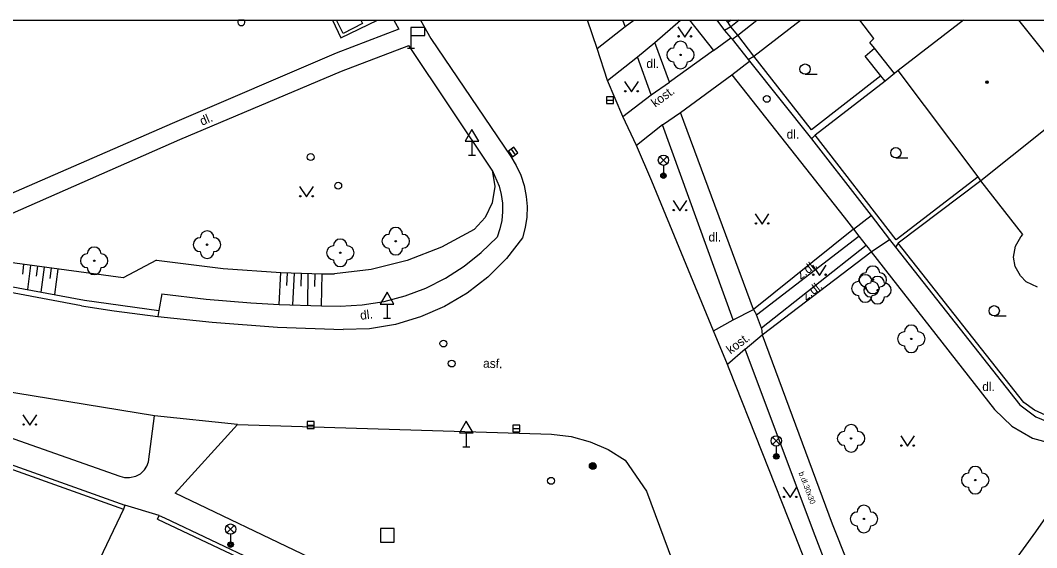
# Model space of a CAD drawing. Extents: x -600309 to -598967, y -1161267 to -1160292.
# Drawn here: x -600107.7 to -600033.9, y -1160330.6 to -1160292.3 of the extents above; entities that cross this region are included whole.
import ezdxf

# ---------------------------------------------------------------- set-up
doc = ezdxf.new("R2010")
doc.units = 0
for name, color, linetype in [('Level 10', 7, 'Continuous'), ('Level 11', 7, 'Continuous'), ('Level 14', 7, 'Continuous'), ('Level 15', 7, 'Continuous'), ('Level 22', 7, 'Continuous'), ('Level 25', 7, 'Continuous'), ('Level 26', 7, 'Continuous'), ('Level 27', 7, 'Continuous'), ('Level 28', 7, 'Continuous'), ('Level 33', 7, 'Continuous'), ('Level 34', 7, 'Continuous'), ('Level 36', 7, 'Continuous'), ('Level 39', 7, 'Continuous'), ('Level 40', 7, 'Continuous'), ('Level 5', 7, 'Continuous'), ('Level 7', 7, 'Continuous'), ('Level 8', 7, 'Continuous'), ('Vrstva 28', 7, 'Continuous'), ('Vrstva 63', 7, 'Continuous')]:
    doc.layers.add(name, color=color, linetype=linetype)

msp = doc.modelspace()

# ---------------------------------------------------------------- linework, layer by layer
at = {"layer": 'Level 10'}
for p, q in [((-600078.6368, -1160292.3474), (-600077.89, -1160293.6599)), ((-600065.81, -1160294.39), (-600066.5144, -1160292.3474))]:
    msp.add_line(p, q, dxfattribs=at)
for points in [[(-600077.89, -1160293.6599), (-600072.07, -1160302.23)], [(-600065.06, -1160296.71), (-600065.81, -1160294.39)], [(-600063.95, -1160299.33), (-600065.06, -1160296.71)], [(-600062.95, -1160301.43), (-600063.95, -1160299.33)], [(-600056.22, -1160317.66), (-600056.35, -1160317.35), (-600057.36, -1160314.89), (-600061.84, -1160304.04), (-600062.95, -1160301.43)], [(-600072.07, -1160302.23), (-600071.68, -1160302.89), (-600071.36, -1160303.6), (-600071.12, -1160304.34), (-600070.9699, -1160305.15), (-600070.9, -1160305.86), (-600070.92, -1160306.64), (-600071.03, -1160307.4), (-600071.2199, -1160308.15)], [(-600071.2199, -1160308.15), (-600072.39, -1160309.65), (-600073.74, -1160310.99), (-600075.25, -1160312.1599), (-600076.89, -1160313.13), (-600078.63, -1160313.89), (-600080.46, -1160314.43), (-600082.34, -1160314.74), (-600084.24, -1160314.81)], [(-600103.23, -1160313.09), (-600115.49, -1160310.79)], [(-600103.23, -1160313.09), (-600100.87, -1160313.44), (-600097.7, -1160313.85)], [(-600097.7, -1160313.85), (-600093.76, -1160314.26), (-600089.01, -1160314.62), (-600084.24, -1160314.81)], [(-600051.43, -1160329.77), (-600056.22, -1160317.66)], [(-600097.95, -1160321.06), (-600115.58, -1160318.2)], [(-600091.93, -1160321.69), (-600097.95, -1160321.06)], [(-600091.93, -1160321.69), (-600069.13, -1160322.4099)], [(-600069.13, -1160322.4099), (-600067.71, -1160322.58), (-600066.32, -1160322.95), (-600065.01, -1160323.52), (-600063.79, -1160324.28)], [(-600063.79, -1160324.28), (-600062.23, -1160326.55)], [(-600062.23, -1160326.55), (-600056.25, -1160342.63)], [(-600047.36, -1160339.81), (-600048.12, -1160338.24), (-600051.43, -1160329.77)]]:
    msp.add_lwpolyline(points, dxfattribs=at)
at = {"layer": 'Level 11'}
for p, q in [((-600085.0266, -1160292.3474), (-600084.42, -1160293.61)), ((-600084.42, -1160293.61), (-600081.7545, -1160292.3474)), ((-600080.5637, -1160292.3474), (-600080.21, -1160292.99)), ((-600063.78, -1160292.8), (-600063.9425, -1160292.3474)), ((-600063.78, -1160292.8), (-600063.1463, -1160292.3474)), ((-600061.62, -1160293.9699), (-600059.7561, -1160292.3474)), ((-600059.1186, -1160292.3474), (-600057.36, -1160294.55)), ((-600055.61, -1160293.42), (-600054.2316, -1160292.3474)), ((-600054.43, -1160294.94), (-600051.0474, -1160292.3474))]:
    msp.add_line(p, q, dxfattribs=at)
for points in [[(-600082.9585, -1160292.3474), (-600082.84, -1160292.58), (-600084.24, -1160293.31), (-600084.7292, -1160292.3474)], [(-600065.81, -1160294.39), (-600063.78, -1160292.8)], [(-600056.12, -1160292.82), (-600056.31, -1160292.51)], [(-600080.21, -1160292.99), (-600084.75, -1160294.74)], [(-600057.36, -1160294.55), (-600056.1, -1160293.62)], [(-600054.43, -1160294.94), (-600055.61, -1160293.42)], [(-600084.37, -1160296.03), (-600079.48, -1160294.18)], [(-600073.44, -1160303.24), (-600079.48, -1160294.18)], [(-600062.89, -1160295.01), (-600061.62, -1160293.9699)], [(-600060.55, -1160296.84), (-600061.62, -1160293.9699)], [(-600046.37, -1160294.94), (-600045.69, -1160294.38)], [(-600084.75, -1160294.74), (-600096.65, -1160299.84)], [(-600065.06, -1160296.71), (-600062.89, -1160295.01)], [(-600061.89, -1160297.77), (-600062.89, -1160295.01)], [(-600057.36, -1160294.55), (-600060.55, -1160296.84)], [(-600045.2199, -1160296.37), (-600046.37, -1160294.94)], [(-600056.03, -1160296.3), (-600054.75, -1160295.32)], [(-600096.11, -1160301.01), (-600084.37, -1160296.03)], [(-600059.76, -1160299.05), (-600056.03, -1160296.3)], [(-600056.03, -1160296.3), (-600047.89, -1160306.65), (-600047.21, -1160307.51)], [(-600061.89, -1160297.77), (-600060.55, -1160296.84)], [(-600063.95, -1160299.33), (-600061.89, -1160297.77)], [(-600061.08, -1160299.93), (-600059.76, -1160299.05)], [(-600054.46, -1160313.36), (-600059.76, -1160299.05)], [(-600096.65, -1160299.84), (-600114.78, -1160307.74)], [(-600061.08, -1160299.93), (-600062.95, -1160301.43)], [(-600055.93, -1160314.1), (-600061.08, -1160299.93)], [(-600108.25, -1160306.36), (-600096.11, -1160301.01)], [(-600073.44, -1160303.24), (-600072.93, -1160304.39), (-600072.78, -1160305), (-600072.69, -1160305.63), (-600072.68, -1160306.26), (-600072.74, -1160306.89), (-600072.87, -1160307.5), (-600073.07, -1160308.1)], [(-600047.21, -1160307.51), (-600045.93, -1160306.53)], [(-600047.21, -1160307.51), (-600054.46, -1160313.36)], [(-600047.21, -1160307.51), (-600046.81, -1160308.02)], [(-600084.46, -1160313.11), (-600082.86, -1160313.02), (-600081.28, -1160312.77), (-600079.74, -1160312.36), (-600078.24, -1160311.79), (-600076.82, -1160311.07), (-600075.4699, -1160310.21), (-600074.2199, -1160309.2199), (-600073.07, -1160308.1)], [(-600054.25, -1160313.74), (-600046.81, -1160308.02)], [(-600046.81, -1160308.02), (-600046.28, -1160308.71)], [(-600045.93, -1160309.1599), (-600044.59, -1160308.26)], [(-600046.28, -1160308.71), (-600053.88, -1160314.71)], [(-600053.83, -1160315.19), (-600045.93, -1160309.1599)], [(-600046.28, -1160308.71), (-600046.15, -1160308.87), (-600045.93, -1160309.1599)], [(-600045.93, -1160309.1599), (-600036.98, -1160320.62)], [(-600097.4099, -1160312.2199), (-600097.63, -1160313.4099)], [(-600097.4099, -1160312.2199), (-600094.19, -1160312.59), (-600090.95, -1160312.87), (-600088.89, -1160312.99), (-600085.82, -1160313.09), (-600084.46, -1160313.11)], [(-600097.63, -1160313.4099), (-600097.7, -1160313.85)], [(-600055.93, -1160314.1), (-600054.46, -1160313.36)], [(-600054.46, -1160313.36), (-600054.25, -1160313.74)], [(-600057.36, -1160314.89), (-600055.93, -1160314.1)], [(-600053.88, -1160314.71), (-600054.25, -1160313.74)], [(-600053.88, -1160314.71), (-600053.83, -1160315.19)], [(-600055.08, -1160316.23), (-600053.83, -1160315.19)], [(-600053.83, -1160315.19), (-600048.76, -1160328.92), (-600047.67, -1160331.66)], [(-600055.08, -1160316.23), (-600056.35, -1160317.35)], [(-600048.59, -1160333.43), (-600050.11, -1160329.48), (-600055.08, -1160316.23)], [(-600114.56, -1160320.48), (-600100.45, -1160325.46)], [(-600036.98, -1160320.62), (-600035.7199, -1160321.83), (-600034.21, -1160322.69), (-600032.53, -1160323.1599), (-600030.79, -1160323.2)], [(-600098.39, -1160324.4), (-600097.95, -1160321.06)], [(-600062.78, -1160347.75), (-600066.6599, -1160344.9099), (-600073.81, -1160339.63), (-600081.26, -1160334.63), (-600086.65, -1160331.38), (-600096.45, -1160326.68), (-600091.93, -1160321.69)], [(-600100.45, -1160325.46), (-600100.12, -1160325.55), (-600099.75, -1160325.56), (-600099.3, -1160325.46), (-600098.9699, -1160325.27), (-600098.67, -1160324.98), (-600098.51, -1160324.73), (-600098.39, -1160324.4)], [(-600030.89, -1160325.06), (-600034, -1160329.49)], [(-600034, -1160329.49), (-600040.85, -1160338.94)]]:
    msp.add_lwpolyline(points, dxfattribs=at)
at = {"layer": 'Level 14'}
for points in [[(-600073.44, -1160303.24), (-600073.25, -1160304.4099), (-600073.43, -1160305.59), (-600073.94, -1160306.6599), (-600074.75, -1160307.53)], [(-600074.75, -1160307.53), (-600077.11, -1160308.82), (-600079.61, -1160309.8), (-600082.21, -1160310.45), (-600084.88, -1160310.76)], [(-600097.8, -1160309.76), (-600100.2199, -1160311.06), (-600114.53, -1160309.11)], [(-600097.8, -1160309.76), (-600092.9699, -1160310.37), (-600088.78, -1160310.6599), (-600085.78, -1160310.75), (-600084.88, -1160310.76)], [(-600115.4099, -1160310.36), (-600103.03, -1160312.67), (-600097.63, -1160313.4099)]]:
    msp.add_lwpolyline(points, dxfattribs=at)
at = {"layer": 'Level 15'}
for points in [[(-600107.44, -1160310.08), (-600107.53, -1160310.78)], [(-600106.94, -1160310.15), (-600107.17, -1160311.9)], [(-600106.44, -1160310.21), (-600106.54, -1160310.93)], [(-600105.95, -1160310.28), (-600106.19, -1160312.08)], [(-600105.45, -1160310.35), (-600105.55, -1160311.09)], [(-600104.96, -1160310.4099), (-600105.2, -1160312.26)], [(-600088.89, -1160312.99), (-600088.78, -1160310.6599)], [(-600088.33, -1160311.61), (-600088.28, -1160310.68)], [(-600087.89, -1160313.02), (-600087.78, -1160310.7)], [(-600087.3, -1160311.65), (-600087.28, -1160310.71)], [(-600086.82, -1160313.06), (-600086.78, -1160310.7199)], [(-600086.3, -1160311.68), (-600086.28, -1160310.74)], [(-600085.82, -1160313.09), (-600085.78, -1160310.75)]]:
    msp.add_lwpolyline(points, dxfattribs=at)
at = {"layer": 'Level 22'}
for centre in [(-600059.76, -1160294.86), (-600080.43, -1160308.39), (-600094.13, -1160308.64), (-600102.32, -1160309.81), (-600084.46, -1160309.23), (-600045.8, -1160311.19), (-600046.35, -1160311.82), (-600045.46, -1160311.94), (-600043.01, -1160315.48), (-600047.38, -1160322.71), (-600038.37, -1160325.74), (-600046.45, -1160328.56)]:
    msp.add_circle(centre, 0.05, dxfattribs=at)
for centre, start, end in [((-600060.26, -1160294.86), 90, 270), ((-600059.76, -1160294.36), 0, 180), ((-600059.26, -1160294.86), 270, 90), ((-600059.76, -1160295.36), 180, 0), ((-600094.13, -1160308.14), 0, 180), ((-600080.43, -1160307.89), 0, 180), ((-600094.63, -1160308.64), 90, 270), ((-600093.63, -1160308.64), 270, 90), ((-600084.46, -1160308.73), 0, 180), ((-600080.93, -1160308.39), 90, 270), ((-600079.93, -1160308.39), 270, 90), ((-600102.32, -1160309.31), 0, 180), ((-600094.13, -1160309.14), 180, 0), ((-600084.96, -1160309.23), 90, 270), ((-600083.96, -1160309.23), 270, 90), ((-600080.43, -1160308.89), 180, 0), ((-600102.82, -1160309.81), 90, 270), ((-600101.82, -1160309.81), 270, 90), ((-600084.46, -1160309.73), 180, 0), ((-600102.32, -1160310.31), 180, 0), ((-600045.8, -1160310.69), 0, 180), ((-600046.85, -1160311.82), 90, 270), ((-600046.35, -1160311.32), 0, 180), ((-600046.3, -1160311.19), 90, 270), ((-600045.46, -1160311.44), 0, 180), ((-600045.85, -1160311.82), 270, 90), ((-600045.3, -1160311.19), 270, 90), ((-600045.96, -1160311.94), 90, 270), ((-600045.8, -1160311.69), 180, 0), ((-600044.96, -1160311.94), 270, 90), ((-600046.35, -1160312.32), 180, 0), ((-600045.46, -1160312.44), 180, 0), ((-600043.51, -1160315.48), 90, 270), ((-600043.01, -1160314.98), 0, 180), ((-600042.51, -1160315.48), 270, 90), ((-600043.01, -1160315.98), 180, 0), ((-600047.88, -1160322.71), 90, 270), ((-600047.38, -1160322.21), 0, 180), ((-600046.88, -1160322.71), 270, 90), ((-600047.38, -1160323.21), 180, 0), ((-600038.87, -1160325.74), 90, 270), ((-600038.37, -1160325.24), 0, 180), ((-600037.87, -1160325.74), 270, 90), ((-600038.37, -1160326.24), 180, 0), ((-600046.45, -1160328.06), 0, 180), ((-600046.95, -1160328.56), 90, 270), ((-600045.95, -1160328.56), 270, 90), ((-600046.45, -1160329.06), 180, 0)]:
    msp.add_arc(centre, 0.5, start, end, dxfattribs=at)
at = {"layer": 'Level 25'}
for radius in [0.25, 0.2, 0.15, 0.1, 0.05]:
    msp.add_circle((-600066.13, -1160324.7199), radius, dxfattribs=at)
at = {"layer": 'Level 26'}
msp.add_lwpolyline([(-600081.54, -1160330.25), (-600080.54, -1160330.25), (-600080.54, -1160329.25), (-600081.54, -1160329.25)], close=True, dxfattribs=at)
at = {"layer": 'Level 27'}
for p, q in [((-600065.13, -1160298.15), (-600064.63, -1160298.15)), ((-600072.0551, -1160301.7165), (-600071.7647, -1160302.1235)), ((-600086.85, -1160321.74), (-600086.35, -1160321.74)), ((-600071.93, -1160321.99), (-600071.43, -1160321.99))]:
    msp.add_line(p, q, dxfattribs=at)
for points in [[(-600065.13, -1160298.4), (-600064.63, -1160298.4), (-600064.63, -1160297.9), (-600065.13, -1160297.9)], [(-600072.2586, -1160301.8617), (-600071.9682, -1160302.2687), (-600071.5612, -1160301.9783), (-600071.8516, -1160301.5713)], [(-600086.85, -1160321.99), (-600086.35, -1160321.99), (-600086.35, -1160321.49), (-600086.85, -1160321.49)], [(-600071.93, -1160322.24), (-600071.43, -1160322.24), (-600071.43, -1160321.74), (-600071.93, -1160321.74)]]:
    msp.add_lwpolyline(points, close=True, dxfattribs=at)
at = {"layer": 'Level 28'}
for centre in [(-600053.5, -1160298.05), (-600086.6, -1160302.28), (-600084.61, -1160304.36), (-600076.9699, -1160315.82), (-600076.37, -1160317.27), (-600069.1599, -1160325.79)]:
    msp.add_circle(centre, 0.25, dxfattribs=at)
at = {"layer": 'Level 33'}
for p, q in [((-600061.265, -1160302.77), (-600060.735, -1160302.24)), ((-600061.265, -1160302.24), (-600060.735, -1160302.77)), ((-600061, -1160302.88), (-600061, -1160303.63)), ((-600053.075, -1160323.16), (-600052.545, -1160322.63)), ((-600053.075, -1160322.63), (-600052.545, -1160323.16)), ((-600052.81, -1160323.27), (-600052.81, -1160324.02)), ((-600092.685, -1160329.56), (-600092.155, -1160329.03)), ((-600092.685, -1160329.03), (-600092.155, -1160329.56)), ((-600092.42, -1160329.67), (-600092.42, -1160330.42))]:
    msp.add_line(p, q, dxfattribs=at)
for centre, radius in [((-600061, -1160302.505), 0.375), ((-600061, -1160303.63), 0.2), ((-600061, -1160303.63), 0.1445), ((-600061, -1160303.63), 0.0876), ((-600052.81, -1160322.895), 0.375), ((-600052.81, -1160324.02), 0.2), ((-600052.81, -1160324.02), 0.1445), ((-600052.81, -1160324.02), 0.0876), ((-600092.42, -1160329.295), 0.375), ((-600092.42, -1160330.42), 0.2), ((-600092.42, -1160330.42), 0.1445), ((-600092.42, -1160330.42), 0.0876)]:
    msp.add_circle(centre, radius, dxfattribs=at)
at = {"layer": 'Level 34'}
for p, q in [((-600079.33, -1160293.46), (-600079.33, -1160294.36)), ((-600079.58, -1160294.36), (-600079.08, -1160294.36)), ((-600074.9, -1160301.132), (-600074.9, -1160302.15)), ((-600075.15, -1160302.15), (-600074.65, -1160302.15)), ((-600081.06, -1160312.962), (-600081.06, -1160313.98)), ((-600081.31, -1160313.98), (-600080.81, -1160313.98)), ((-600075.31, -1160322.312), (-600075.31, -1160323.33)), ((-600075.56, -1160323.33), (-600075.06, -1160323.33))]:
    msp.add_line(p, q, dxfattribs=at)
for points in [[(-600079.33, -1160293.46), (-600078.33, -1160293.46), (-600078.33, -1160292.86), (-600079.33, -1160292.86)], [(-600075.4, -1160301.132), (-600074.4, -1160301.132), (-600074.9, -1160300.266)], [(-600081.56, -1160312.962), (-600080.56, -1160312.962), (-600081.06, -1160312.096)], [(-600075.81, -1160322.312), (-600074.81, -1160322.312), (-600075.31, -1160321.446)]]:
    msp.add_lwpolyline(points, close=True, dxfattribs=at)
at = {"layer": 'Level 36'}
for p, q in [((-600050.7199, -1160296.265), (-600049.8449, -1160296.265)), ((-600044.13, -1160302.335), (-600043.255, -1160302.335)), ((-600036.99, -1160313.815), (-600036.115, -1160313.815))]:
    msp.add_line(p, q, dxfattribs=at)
for points in [[(-600059.95, -1160292.81), (-600059.45, -1160293.56), (-600058.95, -1160292.81)], [(-600063.82, -1160296.8), (-600063.32, -1160297.55), (-600062.82, -1160296.8)], [(-600087.4099, -1160304.42), (-600086.9099, -1160305.17), (-600086.4099, -1160304.42)], [(-600060.3, -1160305.43), (-600059.8, -1160306.18), (-600059.3, -1160305.43)], [(-600054.34, -1160306.4), (-600053.84, -1160307.15), (-600053.34, -1160306.4)], [(-600050.18, -1160310.12), (-600049.68, -1160310.87), (-600049.18, -1160310.12)], [(-600107.49, -1160321), (-600106.99, -1160321.75), (-600106.49, -1160321)], [(-600043.78, -1160322.53), (-600043.28, -1160323.28), (-600042.78, -1160322.53)], [(-600052.31, -1160326.26), (-600051.81, -1160327.01), (-600051.31, -1160326.26)]]:
    msp.add_lwpolyline(points, dxfattribs=at)
for centre, radius in [((-600059.9002, -1160293.5098), 0.05), ((-600059.0008, -1160293.5098), 0.05), ((-600050.72, -1160295.8899), 0.375), ((-600063.7702, -1160297.4998), 0.05), ((-600062.8708, -1160297.4998), 0.05), ((-600044.1301, -1160301.9599), 0.375), ((-600087.3601, -1160305.1198), 0.05), ((-600086.4607, -1160305.1198), 0.05), ((-600060.2502, -1160306.1298), 0.05), ((-600059.3508, -1160306.1298), 0.05), ((-600054.2902, -1160307.0998), 0.05), ((-600053.3908, -1160307.0998), 0.05), ((-600050.1302, -1160310.8198), 0.05), ((-600049.2308, -1160310.8198), 0.05), ((-600036.9901, -1160313.4399), 0.375), ((-600107.4402, -1160321.6998), 0.05), ((-600106.5408, -1160321.6998), 0.05), ((-600043.7302, -1160323.2298), 0.05), ((-600042.8308, -1160323.2298), 0.05), ((-600052.2602, -1160326.9598), 0.05), ((-600051.3608, -1160326.9598), 0.05)]:
    msp.add_circle(centre, radius, dxfattribs=at)
at = {"layer": 'Level 39'}
for radius in [0.09, 0.0398]:
    msp.add_circle((-600037.52, -1160296.84), radius, dxfattribs=at)
at = {"layer": 'Level 5'}
for p, q in [((-600045.73, -1160293.6599), (-600046.7474, -1160292.3474)), ((-600039.2307, -1160292.3474), (-600043.9699, -1160295.99)), ((-600035.2361, -1160292.3474), (-600030.62, -1160298.12))]:
    msp.add_line(p, q, dxfattribs=at)
for points in [[(-600046.01, -1160293.9699), (-600045.73, -1160293.6599)], [(-600045.69, -1160294.38), (-600046.01, -1160293.9699)], [(-600044.2199, -1160296.2), (-600045.69, -1160294.38)], [(-600043.9699, -1160295.99), (-600044.2199, -1160296.2)], [(-600038.1599, -1160303.7199), (-600043.9699, -1160295.99)], [(-600031.02, -1160298.45), (-600037.9699, -1160304.01)], [(-600037.9699, -1160304.01), (-600038.1599, -1160303.7199)], [(-600034.9099, -1160307.9), (-600037.9699, -1160304.01)], [(-600035.44, -1160308.74), (-600035.06, -1160308.07)], [(-600035.06, -1160308.07), (-600034.9099, -1160307.9)], [(-600035.58, -1160309.54), (-600035.44, -1160308.74)], [(-600035.46, -1160310.2199), (-600035.58, -1160309.54)], [(-600035.09, -1160310.9099), (-600035.46, -1160310.2199)], [(-600034.67, -1160311.34), (-600035.09, -1160310.9099)], [(-600033.84, -1160311.7199), (-600034.67, -1160311.34)]]:
    msp.add_lwpolyline(points, dxfattribs=at)
at = {"layer": 'Level 7'}
for p, q in [((-600057.1296, -1160292.3474), (-600056.57, -1160293.08)), ((-600056.31, -1160292.51), (-600056.4378, -1160292.3474)), ((-600056.0983, -1160292.3474), (-600056.31, -1160292.51)), ((-600055.503, -1160292.3474), (-600056.12, -1160292.82))]:
    msp.add_line(p, q, dxfattribs=at)
for points in [[(-600056.12, -1160292.82), (-600056.57, -1160293.08)], [(-600055.61, -1160293.42), (-600056.12, -1160292.82)], [(-600056.57, -1160293.08), (-600056.1, -1160293.62)], [(-600056.1, -1160293.62), (-600056.02, -1160293.7199)], [(-600056.02, -1160293.7199), (-600055.61, -1160293.42)], [(-600054.85, -1160295.19), (-600054.43, -1160294.94)], [(-600045.2199, -1160296.37), (-600050.26, -1160300.31), (-600054.43, -1160294.94)], [(-600054.85, -1160295.19), (-600054.75, -1160295.32)], [(-600054.75, -1160295.32), (-600050.25, -1160300.95)], [(-600044.9099, -1160296.76), (-600045.2199, -1160296.37)], [(-600044.2199, -1160296.2), (-600044.9099, -1160296.76)], [(-600044.9099, -1160296.76), (-600050, -1160300.68)], [(-600050, -1160300.68), (-600050.25, -1160300.95)], [(-600050.25, -1160300.95), (-600046.61, -1160305.65), (-600045.93, -1160306.53)], [(-600038.1599, -1160303.7199), (-600044.12, -1160308.3), (-600050, -1160300.68)], [(-600037.9699, -1160304.01), (-600043.9699, -1160308.54)], [(-600045.93, -1160306.53), (-600044.91, -1160307.85), (-600044.59, -1160308.26)], [(-600044.59, -1160308.26), (-600044.15, -1160308.83)], [(-600043.9699, -1160308.54), (-600044.15, -1160308.83)], [(-600044.15, -1160308.83), (-600035.13, -1160320.28)], [(-600034.83, -1160320.1), (-600043.9699, -1160308.54)], [(-600027.35, -1160319.65), (-600028.18, -1160320.4), (-600029.35, -1160321.04), (-600030.71, -1160321.38), (-600031, -1160321.4099), (-600031.75, -1160321.4), (-600033, -1160321.15), (-600034.06, -1160320.6599), (-600034.83, -1160320.1)], [(-600035.13, -1160320.28), (-600033.9699, -1160321.14), (-600032.87, -1160321.61), (-600031.6, -1160321.81), (-600031.09, -1160321.81), (-600030.89, -1160321.8)], [(-600115.84, -1160322.25), (-600115.74, -1160321.97), (-600100.09, -1160327.56)], [(-600115.84, -1160322.25), (-600100.19, -1160327.84)], [(-600100.09, -1160327.56), (-600100.19, -1160327.84)], [(-600100.19, -1160327.84), (-600110.06, -1160348.53)], [(-600097.73, -1160328.57), (-600097.6, -1160328.3)], [(-600097.6, -1160328.3), (-600097.22, -1160328.48), (-600090.49, -1160331.67), (-600090.62, -1160331.94)], [(-600097.73, -1160328.57), (-600090.62, -1160331.94)]]:
    msp.add_lwpolyline(points, dxfattribs=at)
at = {"layer": 'Level 8'}
for points in [[(-600056.02, -1160293.7199), (-600054.85, -1160295.19)], [(-600097.6, -1160328.3), (-600100.09, -1160327.56)]]:
    msp.add_lwpolyline(points, dxfattribs=at)
at = {"layer": 'Vrstva 28'}
msp.add_line((-600091.4281, -1160292.3474), (-600091.8519, -1160292.3474), dxfattribs=at)
msp.add_arc((-600091.64, -1160292.48), 0.25, 147.963432, 32.036568, dxfattribs=at)
at = {"layer": 'Vrstva 63'}
msp.add_lwpolyline([(-600308.541, -1160292.3474), (-598967.1085, -1160292.3474), (-598967.1085, -1161267.0314), (-600308.541, -1161267.0314)], close=True, dxfattribs=at)

# ---------------------------------------------------------------- texts
at = {"layer": 'Level 40'}
for p in [(-600062.24, -1160295.81), (-600062.24, -1160295.81), (-600052.06, -1160300.94), (-600052.06, -1160300.94), (-600057.73, -1160308.4099), (-600057.73, -1160308.4099), (-600037.86, -1160319.27), (-600037.86, -1160319.27)]:
    msp.add_text('dl.', height=0.65, dxfattribs=at).set_placement(p)
for s, height, rotation, p in [('kost.', 0.65, 36.88, (-600061.59, -1160298.7)), ('dl.', 0.65, 23.198592, (-600094.49, -1160300.01)), ('z.dl.', 0.65, 37.28, (-600051.05, -1160311.2)), ('z.dl.', 0.65, 37.28, (-600050.66, -1160312.72)), ('dl.', 0.64999, 7.047197, (-600082.98, -1160314.1)), ('kost.', 0.65, 36.88, (-600056.13, -1160316.62)), ('asf.', 0.64999, 358.191261, (-600074.1, -1160317.57)), ('b.dl.30x30', 0.4, 291.047231, (-600051.2, -1160325.22))]:
    msp.add_text(s, height=height, rotation=rotation, dxfattribs=at).set_placement(p)

doc.saveas('drawing.dxf')
